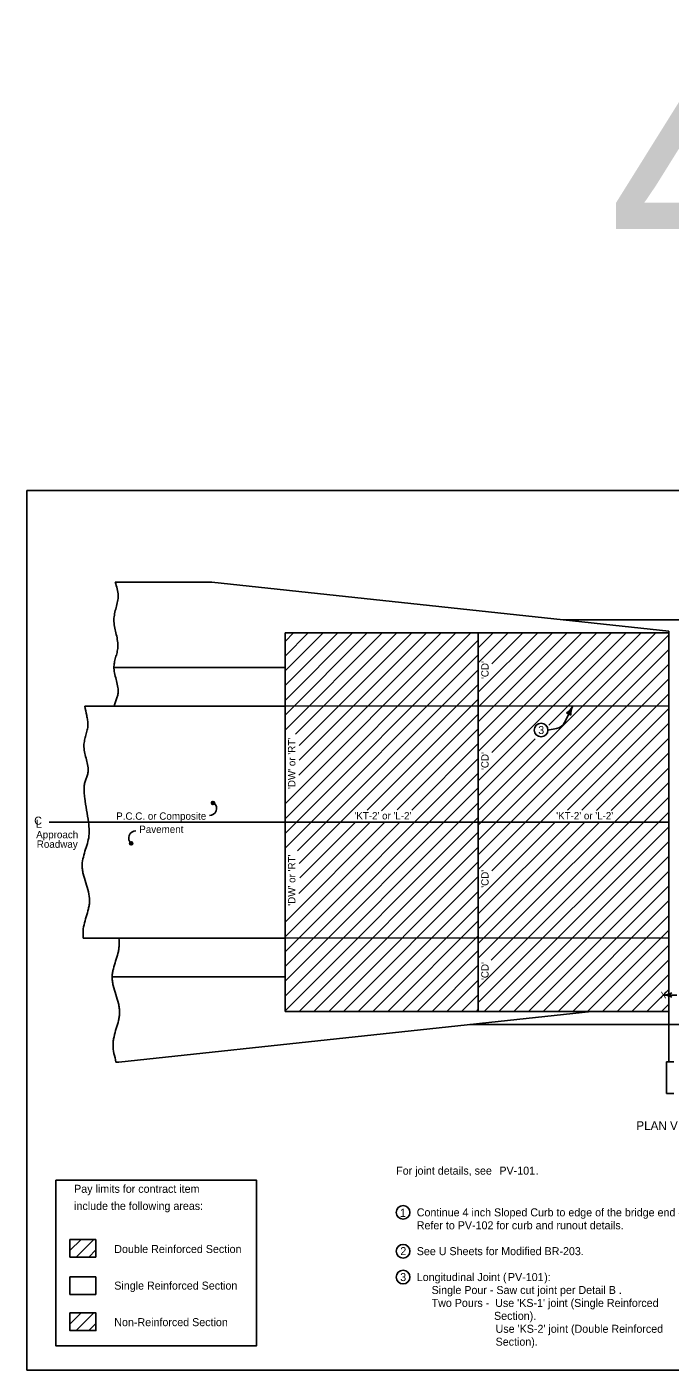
# Model space of a CAD drawing. Extents: x 5546 to 81668, y 3174 to 15999.
# Drawn here: x 20933 to 22411, y 7924 to 11009 of the extents above; entities that cross this region are included whole.
import ezdxf

# ---------------------------------------------------------------- set-up
doc = ezdxf.new("R2010")
doc.units = 0
for name, color, linetype in [('Level 61', 7, 'Continuous'), ('PS_BOLT', 7, 'Continuous'), ('PS_CONST', 7, 'Continuous'), ('PS_DIM', 7, 'Continuous'), ('Table Border', 7, 'Continuous'), ('tdCoShieldCoRte', 7, 'Continuous')]:
    doc.layers.add(name, color=color, linetype=linetype)

msp = doc.modelspace()

# ---------------------------------------------------------------- linework, layer by layer
for p, q in [((21357.6, 9734), (21135.8, 9734)), ((22407.5, 9621.3), (21357.6, 9734)), ((23596.7, 9647.3), (22164.9, 9647.3)), ((21525.7, 9537.8), (21132.6, 9537.8)), ((21065.4, 9449), (21525.7, 9449)), ((20983.8, 9182.6), (21074.2, 9182.6)), ((21074.2, 9182.6), (21525.7, 9182.6)), ((21525.7, 8916.2), (21062.2, 8916.2)), ((21525.7, 8827.4), (21128.6, 8827.4)), ((21143.5, 8631.2), (22229.8, 8747.8)), ((21950.3, 8717.8), (23382.5, 8717.9))]:
    msp.add_line(p, q)
for points in [[(21135.8, 9734), (21140.1, 9718.8), (21142.4, 9703.5), (21142, 9696.5), (21140.9, 9689.5), (21137.6, 9675.4), (21134.2, 9661.3), (21132.6, 9647.3), (21134, 9632.2), (21137.2, 9617.2), (21140.4, 9602.1), (21141.7, 9587.1), (21140.3, 9575.3), (21137.3, 9563.5), (21134.2, 9551.8), (21132.6, 9540), (21134, 9525.3), (21137.6, 9510.6), (21141.1, 9495.8), (21142.4, 9481.1), (21140.8, 9472.3), (21137.9, 9463.5), (21134.9, 9454.7), (21133.6, 9449)], [(21065.4, 9449), (21070.1, 9427.5), (21072, 9416.8), (21072.7, 9406.1), (21071.3, 9394.3), (21068.3, 9382.5), (21065.2, 9370.8), (21063.6, 9359), (21065, 9344.3), (21068.6, 9329.6), (21072.1, 9314.9), (21073.4, 9300.2), (21071.8, 9291.3), (21068.8, 9282.5), (21065.8, 9273.7), (21064.2, 9264.8), (21064.2, 9251.3), (21065.4, 9237.7), (21069.8, 9210.2), (21074.2, 9182.7), (21075.7, 9162.3), (21075.6, 9155.6), (21072.7, 9137.9), (21067.5, 9120.2), (21062.3, 9102.5), (21059.6, 9084.7), (21060.1, 9074.4), (21061.9, 9064), (21067.9, 9043.3), (21074, 9022.6), (21076.6, 9001.9), (21075.8, 8992.7), (21074, 8983.4), (21068.9, 8965), (21063.9, 8946.5), (21061.6, 8928), (21062.2, 8916.2)], [(21144.2, 8916.2), (21144.6, 8899), (21143.6, 8890.1), (21141.7, 8881.3), (21136.5, 8863.6), (21131.3, 8845.9), (21129.4, 8837.1), (21128.9, 8832.6), (21128.6, 8828.1), (21129.1, 8817.8), (21131, 8807.4), (21137, 8786.7), (21143, 8766), (21145, 8755.7), (21145.5, 8750.5), (21145.6, 8745.3), (21144.8, 8736.1), (21143.1, 8726.8), (21137.9, 8708.4), (21132.9, 8689.9), (21131.2, 8680.7), (21130.7, 8676.1), (21130.6, 8671.4), (21132.5, 8651.5), (21136.8, 8631.6), (21136.8, 8631.2)]]:
    msp.add_spline(points, degree=3)
at = {"layer": 'Level 61'}
msp.add_lwpolyline([(20932.5, 9944), (24067.5, 9944), (24067.5, 7924), (20932.5, 7924)], close=True, dxfattribs=at)
at = {"layer": 'PS_BOLT'}
for p, q in [((22168, 9411.5), (22186.7, 9449.3)), ((22129.7, 9394.2), (22149.2, 9397.5)), ((22394.6, 8785.6), (22425.9, 8785.6)), ((21031.6, 8224.3), (21091.3, 8224.3)), ((21031.6, 8183.8), (21031.6, 8224.3)), ((21091.3, 8224.3), (21091.3, 8183.8)), ((21091.3, 8183.8), (21031.6, 8183.8)), ((21031.6, 8138.2), (21091.3, 8138.2)), ((21031.6, 8097.8), (21031.6, 8138.2)), ((21091.3, 8138.2), (21091.3, 8097.8)), ((21091.3, 8097.8), (21031.6, 8097.8))]:
    msp.add_line(p, q, dxfattribs=at)
for centre, radius, start, end in [((22145, 9422.8), 25.7, 279.5323, 333.7542), ((21352.1, 9214.2), 16.5, 270, 48.6908), ((21183.2, 9146.3), 16.5, 90, 228.691)]:
    msp.add_arc(centre, radius, start, end, dxfattribs=at)
at = {"layer": 'PS_DIM'}
for p, q in [((21525.7, 9190.6), (21952.4, 9617.3)), ((21525.7, 9224.5), (21918.5, 9617.3)), ((21525.7, 9394.2), (21748.8, 9617.3)), ((21525.7, 9428.2), (21714.8, 9617.3)), ((21525.7, 9462.1), (21680.9, 9617.3)), ((21525.7, 9496.1), (21646.9, 9617.3)), ((21525.7, 9530), (21613, 9617.3)), ((21525.7, 9563.9), (21579.1, 9617.3)), ((21525.7, 9597.9), (21545.1, 9617.3)), ((21525.7, 9156.6), (21969.7, 9600.6)), ((21549.9, 9384.5), (21782.7, 9617.3)), ((21557.5, 9290.3), (21884.5, 9617.3)), ((21557.9, 9324.6), (21850.6, 9617.3)), ((21558, 9358.7), (21816.7, 9617.3)), ((21969.7, 9209.3), (22377.7, 9617.3)), ((21969.7, 9277.2), (22309.8, 9617.3)), ((21969.7, 9345.1), (22241.9, 9617.3)), ((21969.7, 9379), (22208, 9617.3)), ((21969.7, 9413), (22174, 9617.3)), ((21969.7, 9446.9), (22140.1, 9617.3)), ((21969.7, 9480.8), (22106.2, 9617.3)), ((21969.7, 9548.7), (22038.3, 9617.3)), ((21969.7, 9582.7), (22004.3, 9617.3)), ((21969.7, 9616.6), (21970.4, 9617.3)), ((21969.7, 9175.4), (22407.5, 9613.2)), ((22000.9, 9342.4), (22275.9, 9617.3)), ((22001.2, 9546.4), (22072.2, 9617.3)), ((22132, 9405.6), (22343.7, 9617.3)), ((22407.5, 8747.8), (22407.5, 9621.3)), ((21525.7, 9122.7), (21969.7, 9566.7)), ((21969.7, 9141.4), (22407.5, 9579.3)), ((21969.7, 9107.5), (22407.5, 9545.3)), ((21554.1, 9117.1), (21969.7, 9532.8)), ((21969.7, 9073.6), (22407.5, 9511.4)), ((21558.5, 9087.6), (21969.7, 9498.8)), ((22001.1, 9071), (22407.5, 9477.4)), ((21525.7, 9449), (22407.5, 9449.5)), ((21714.6, 9209.8), (21969.7, 9464.9)), ((22174.5, 9210.4), (22407.5, 9443.5)), ((21747.2, 9208.4), (21969.7, 9430.9)), ((21783.4, 9210.7), (21969.7, 9397)), ((22207.8, 9209.8), (22407.5, 9409.6)), ((21816.7, 9210.1), (21969.7, 9363.1)), ((21969.7, 9243.3), (22100.4, 9374)), ((22241.2, 9209.4), (22407.5, 9375.6)), ((21525.7, 8885.1), (21969.7, 9329.1)), ((22275.4, 9209.6), (22407.5, 9341.7)), ((21525.7, 8851.2), (21969.7, 9295.2)), ((21969.7, 8869.9), (22407.5, 9307.7)), ((21525.7, 8817.2), (21969.7, 9261.2)), ((21999, 8865.3), (22407.5, 9273.8)), ((21525.7, 8783.3), (21969.7, 9227.3)), ((21969.7, 8802), (22407.5, 9239.9)), ((21969.7, 8768.1), (22407.5, 9205.9)), ((21525.7, 8749.4), (21969.7, 9193.4)), ((21525.7, 8919.1), (21789.3, 9182.7)), ((21525.7, 8953), (21755.2, 9182.6)), ((21557.6, 9018.8), (21721.3, 9182.6)), ((21559.4, 9054.6), (21687.4, 9182.6)), ((21969.7, 9005.7), (22146.7, 9182.7)), ((21969.7, 8971.7), (22180.5, 9182.6)), ((21969.7, 8937.8), (22214.4, 9182.5)), ((21969.7, 8903.8), (22248.3, 9182.4)), ((21983.4, 8747.8), (22407.5, 9172)), ((21558.1, 8747.8), (21969.7, 9159.4)), ((22017.3, 8747.8), (22407.5, 9138)), ((21592, 8747.8), (21969.7, 9125.5)), ((22051.2, 8747.8), (22407.5, 9104.1)), ((21626, 8747.8), (21969.7, 9091.5)), ((21659.9, 8747.8), (21969.7, 9057.6)), ((22085.2, 8747.8), (22407.5, 9070.2)), ((21693.8, 8747.8), (21969.7, 9023.6)), ((22119.1, 8747.8), (22407.5, 9036.2)), ((21727.8, 8747.8), (21969.7, 8989.7)), ((22153.1, 8747.8), (22407.5, 9002.3)), ((21761.7, 8747.8), (21969.7, 8955.8)), ((22187, 8747.8), (22407.5, 8968.3)), ((21525.7, 8916.2), (22407.5, 8916.7)), ((21795.7, 8747.8), (21969.7, 8921.8)), ((22220.9, 8747.8), (22407.5, 8934.4)), ((21829.6, 8747.8), (21969.7, 8887.9)), ((22254.9, 8747.8), (22407.5, 8900.4)), ((22288.8, 8747.8), (22407.5, 8866.5)), ((21863.6, 8747.8), (21969.7, 8853.9)), ((22322.8, 8747.8), (22407.5, 8832.6)), ((21897.5, 8747.8), (21969.7, 8820)), ((22356.7, 8747.8), (22407.5, 8798.6)), ((21931.4, 8747.8), (21969.7, 8786.1)), ((22390.7, 8747.8), (22407.5, 8764.7)), ((21965.4, 8747.8), (21969.7, 8752.1)), ((22407.5, 8747.8), (22407.5, 8632.1)), ((22402.4, 8632.1), (22418.8, 8632.1)), ((22402.4, 8632.1), (22402.4, 8559.7)), ((22402.4, 8559.7), (22418.8, 8559.7)), ((21031.6, 8224.3), (21091.3, 8224.3)), ((21031.6, 8224.3), (21031.6, 8183.8)), ((21031.6, 8198.7), (21057.3, 8224.3)), ((21045.9, 8183.8), (21086.4, 8224.3)), ((21091.3, 8224.3), (21091.3, 8183.8)), ((21091.3, 8183.8), (21031.6, 8183.8)), ((21075, 8183.8), (21091.3, 8200.2)), ((21031.6, 8138.2), (21091.3, 8138.2)), ((21031.6, 8138.2), (21031.6, 8097.8)), ((21091.3, 8138.2), (21091.3, 8097.8)), ((21091.3, 8097.8), (21031.6, 8097.8)), ((21031.6, 8029.6), (21057.3, 8055.3)), ((21045.9, 8014.8), (21086.4, 8055.3)), ((21075, 8014.8), (21091.3, 8031.2))]:
    msp.add_line(p, q, dxfattribs=at)
for points in [[(21360.5, 9223.3), (21359.3, 9223.8), (21357.4, 9224.4), (21357, 9226.3), (21357.3, 9228), (21358.5, 9229.6), (21360.3, 9229.4), (21362.2, 9229.1), (21363.1, 9227.6), (21363.3, 9226), (21362.2, 9223.9), (21360.8, 9223.8), (21358.9, 9224.2), (21357.3, 9225.5), (21357.4, 9227.3), (21358.6, 9228.7), (21360.3, 9228.9), (21362.2, 9228.5), (21362.5, 9227.4), (21362.9, 9226.2), (21362, 9224.6), (21360.6, 9224.6), (21359, 9224.9), (21357.9, 9225.8), (21358.5, 9227.3), (21359.6, 9228.3), (21361.2, 9228.3), (21361.6, 9227.5), (21362.2, 9226.5), (21361.4, 9225.2), (21360.2, 9225), (21359.1, 9225.5), (21359.1, 9226.7), (21359.6, 9227.5), (21360.7, 9227.8), (21361.2, 9227.4), (21361.5, 9226.7), (21361, 9225.8), (21360.2, 9225.6), (21359.5, 9226), (21359.6, 9226.7), (21360.1, 9227.1), (21360.9, 9227.1), (21360.9, 9226.5), (21360.2, 9226.2)], [(21172.5, 9130.5), (21171.3, 9131.1), (21169.4, 9131.7), (21169.1, 9133.6), (21169.3, 9135.3), (21170.5, 9136.9), (21172.3, 9136.7), (21174.2, 9136.4), (21175.2, 9134.9), (21175.3, 9133.3), (21174.2, 9131.2), (21172.8, 9131), (21170.9, 9131.5), (21169.4, 9132.7), (21169.4, 9134.5), (21170.6, 9136), (21172.3, 9136.2), (21174.2, 9135.8), (21174.5, 9134.7), (21174.9, 9133.4), (21174, 9131.9), (21172.6, 9131.9), (21171, 9132.2), (21169.9, 9133), (21170.5, 9134.6), (21171.7, 9135.5), (21173.3, 9135.6), (21173.7, 9134.7), (21174.2, 9133.8), (21173.4, 9132.5), (21172.2, 9132.2), (21171.2, 9132.8), (21171.1, 9134), (21171.6, 9134.8), (21172.7, 9135.1), (21173.2, 9134.7), (21173.5, 9134), (21173, 9133.1), (21172.2, 9132.9), (21171.5, 9133.3), (21171.6, 9134), (21172.2, 9134.4), (21172.9, 9134.3), (21172.9, 9133.8), (21172.2, 9133.5)]]:
    msp.add_lwpolyline(points, dxfattribs=at)
for points in [[(20998.9, 8360.3), (21460.2, 8360.3), (21460.2, 7980), (20998.9, 7980)], [(21031.6, 8055.3), (21091.3, 8055.3), (21091.3, 8014.8), (21031.6, 8014.8)]]:
    msp.add_lwpolyline(points, close=True, dxfattribs=at)
for centre, radius in [((22114, 9394.2), 15.7), ((21360.2, 9226.6), 3.62), ((21172.3, 9133.9), 3.62), ((21796.9, 8286.4), 15.7), ((21796.9, 8197.2), 15.7), ((21796.9, 8137.8), 15.7)]:
    msp.add_circle(centre, radius, dxfattribs=at)
for centre, radius, start, end in [((22146.9, 9469), 44.4, 305.682, 333.7545), ((22226.5, 9429.7), 44.4, 153.7545, 181.8269), ((22170.2, 9416), 17.1, 46.0211, 81.4878), ((22394.6, 8827.9), 42.3, 270, 298.0725), ((22394.6, 8743.3), 42.3, 61.9275, 90)]:
    msp.add_arc(centre, radius, start, end, dxfattribs=at)
at = {"layer": 'Table Border'}
for p, q in [((21525.7, 8747.8), (21525.7, 9617.3)), ((21525.7, 9617.3), (21969.7, 9617.3)), ((21525.7, 9537.8), (21525.7, 9617.3)), ((21525.7, 9617.3), (22407.5, 9617.3)), ((21969.7, 8747.8), (21969.7, 9617.3)), ((21969.7, 9617.3), (22407.5, 9617.3)), ((21525.7, 9449), (21525.7, 9537.8)), ((21525.7, 9182.6), (21525.7, 8747.8)), ((21525.7, 9182.6), (22407.5, 9182.6)), ((21525.7, 8747.8), (21525.7, 8827.4)), ((22229.8, 8747.8), (21525.7, 8747.8)), ((21525.7, 8747.8), (22407.5, 8747.8)), ((21136.8, 8631.2), (21143.5, 8631.2))]:
    msp.add_line(p, q, dxfattribs=at)

# ---------------------------------------------------------------- texts
at = {"layer": 'PS_BOLT'}
for s, height, p in [("'CD'", 16.8, (21993.4, 9511.4)), ("'DW' or 'RT'", 16.884, (21549.5, 9258.7)), ("'CD'", 16.8, (21993.4, 9302.4)), ("'DW' or 'RT'", 16.884, (21549.5, 8990.6)), ("'CD'", 16.8, (21993.4, 9032)), ("'CD'", 16.8, (21993.4, 8820.1))]:
    msp.add_text(s, height=height, rotation=90, dxfattribs=at).set_placement(p)
for s, height, p in [('3', 18.4, (22107.5, 9385)), ('C', 18.5, (20949.4, 9176.8)), ('P.C.C. or Composite', 16.884, (21137.7, 9188.1)), ("'KT-2' or 'L-2'", 16.8, (21685.2, 9188.9)), ("'KT-2' or 'L-2'", 16.8, (22148.9, 9188.9)), ('Approach', 16.88, (20953.9, 9145.6)), ('L', 18.5, (20953.3, 9169.6)), ('Pavement', 16.88, (21190.7, 9157.7)), ('Roadway', 16.88, (20955.3, 9123.7)), ('X', 16, (22387.9, 8777.6)), ('For joint details, see ', 18.375, (21781.1, 8373)), ('PV-101', 18.37, (22018.3, 8373)), ('PV-101', 18.37, (22018.3, 8373)), ('.', 18.4, (22101.6, 8373)), ('Pay limits for contract item', 18.375, (21041.1, 8331.3)), ('include the following areas:', 18.375, (21041.1, 8292)), ('1', 18.4, (21789.7, 8276.1)), ('Continue 4 inch Sloped Curb to edge of the bridge end drain.', 18.375, (21828.4, 8277.2)), ('Refer to PV-102 for curb and runout details.', 18.375, (21828.4, 8247.5)), ('Double Reinforced Section', 18.375, (21133.4, 8193)), ('2', 18.4, (21790.6, 8188.1)), ('See U Sheets for Modified BR-203.', 18.375, (21828.4, 8188.1)), ('3', 18.4, (21790.4, 8128.6)), ('Longitudinal Joint (', 18.375, (21828.4, 8128.6)), ('PV-101', 18.37, (22037.9, 8128.6)), ('PV-101', 18.37, (22037.9, 8128.6)), ('):', 18.37, (22121.1, 8128.6)), ('Single Reinforced Section', 18.375, (21133.4, 8109)), ('     Single Pour - Saw cut joint per Detail B .', 18.375, (21828.4, 8098.9)), ("     Two Pours -  Use 'KS-1' joint (Single Reinforced", 18.375, (21828.4, 8069.2)), ('                          Section).', 18.375, (21828.4, 8039.5)), ('Non-Reinforced Section', 18.375, (21133.4, 8025)), ("     Use 'KS-2' joint (Double Reinforced", 18.375, (21975.4, 8009.8)), ('     Section).', 18.375, (21975.4, 7980.1))]:
    msp.add_text(s, height=height, dxfattribs=at).set_placement(p)
at = {"layer": 'PS_CONST'}
msp.add_text('PLAN VIEW', height=20, dxfattribs=at).set_placement((22333, 8475.6))
at = {"layer": 'tdCoShieldCoRte'}
msp.add_text('4', height=600, dxfattribs=at).set_placement((22267.6, 10409.2))

doc.saveas('drawing.dxf')
